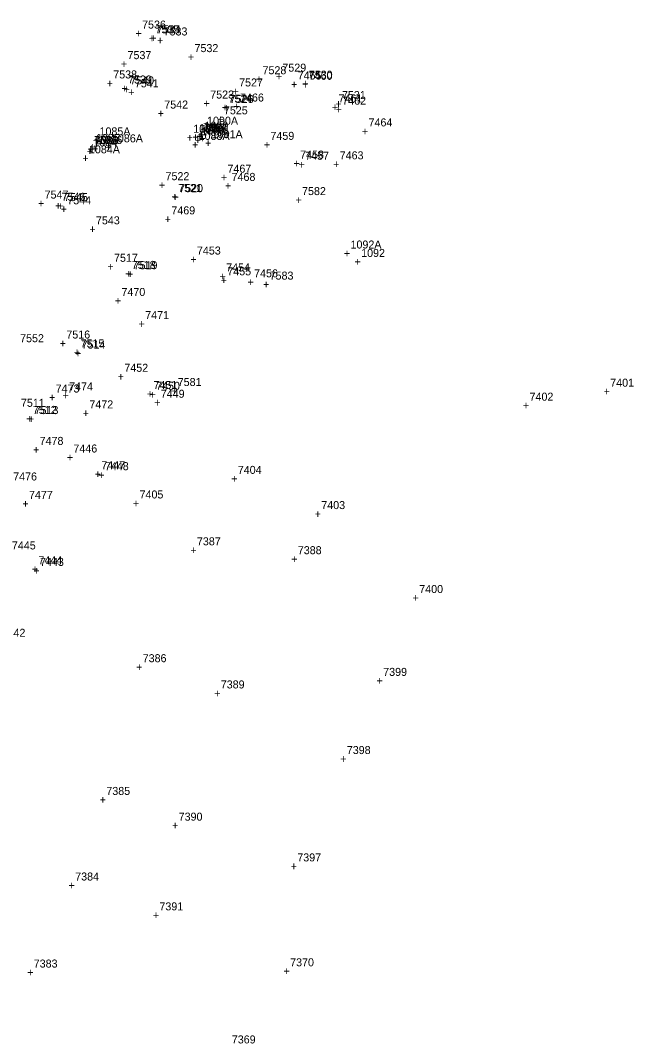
# Model space of a CAD drawing. Extents: x 1136220 to 1137808, y 528804 to 531215.
# Drawn here: x 1137616.8 to 1137808.2, y 530895.5 to 531215.1 of the extents above; entities that cross this region are included whole.
import ezdxf

# ---------------------------------------------------------------- set-up
doc = ezdxf.new("R2010")
doc.units = 0
for name, color, linetype in [('S_Curb_Type_1', 7, 'Continuous'), ('S_Drainage_CB', 7, 'Continuous'), ('S_Drainage_Culvert_Top', 7, 'Continuous'), ('S_Drainage_Invert', 7, 'Continuous'), ('S_Drainage_Sump', 7, 'Continuous'), ('S_Fencing_PostAndRail', 7, 'Continuous'), ('S_Ground_Elevation', 7, 'Continuous'), ('S_Property_IronPipeFound', 7, 'Continuous'), ('S_Property_Walkways', 7, 'Continuous'), ('S_Roadway_Centerline', 7, 'Continuous'), ('S_Roadway_Drive_Paved', 7, 'Continuous'), ('S_Roadway_Edge_Pavement', 7, 'Continuous'), ('S_Roadway_Edge_TW', 7, 'Continuous'), ('S_Roadway_Sidewalks', 7, 'Continuous'), ('S_Traffic_Sign_SinglePost', 7, 'Continuous'), ('S_Trees_Decid_Pay', 7, 'Continuous'), ('S_Trees_TreeLine', 7, 'Continuous'), ('S_Utilities_GuyWire3', 7, 'Continuous'), ('S_Utilities_Pole_Power', 7, 'Continuous')]:
    doc.layers.add(name, color=color, linetype=linetype)

msp = doc.modelspace()

# ---------------------------------------------------------------- texts
at = {"layer": 'S_Curb_Type_1'}
for s, p in [('7535', (1137658.9, 531211.07)), ('+', (1137656.84, 531208.32)), ('7539', (1137650.37, 531195.42)), ('+', (1137648.31, 531192.67)), ('7526', (1137682.11, 531189.32)), ('+', (1137680.05, 531186.57)), ('7525', (1137680.3, 531185.79)), ('+', (1137678.24, 531183.04)), ('7546', (1137629.62, 531158.77)), ('7520', (1137666.34, 531161.47)), ('+', (1137627.56, 531156.02)), ('+', (1137664.28, 531158.72)), ('7519', (1137652.11, 531137.4)), ('+', (1137650.05, 531134.65)), ('7514', (1137635.86, 531112.61)), ('+', (1137633.79, 531109.86)), ('7513', (1137621.18, 531092.15)), ('+', (1137619.12, 531089.4))]:
    msp.add_text(s, height=2.5, dxfattribs=at).set_placement(p)
at = {"layer": 'S_Drainage_CB'}
for s, p in [('7584', (1137673.8, 531180.5)), ('7585', (1137639.8, 531176.5)), ('+', (1137671.74, 531177.75)), ('+', (1137637.74, 531173.75))]:
    msp.add_text(s, height=2.5, dxfattribs=at).set_placement(p)
at = {"layer": 'S_Drainage_Culvert_Top'}
for s, p in [('1090A', (1137675.05, 531182.54)), ('1085A', (1137641.45, 531179.21)), ('1089A', (1137670.74, 531180.03)), ('1088A', (1137672.41, 531177.81)), ('+', (1137672.99, 531179.79)), ('1091A', (1137676.48, 531178.34)), ('+', (1137639.39, 531176.46)), ('1086A', (1137645.34, 531177.04)), ('+', (1137668.68, 531177.28)), ('+', (1137670.35, 531175.06)), ('+', (1137674.42, 531175.59)), ('1084A', (1137638.16, 531173.61)), ('+', (1137643.28, 531174.29)), ('+', (1137636.1, 531170.86)), ('1092A', (1137719.84, 531143.87)), ('+', (1137717.78, 531141.12))]:
    msp.add_text(s, height=2.5, dxfattribs=at).set_placement(p)
at = {"layer": 'S_Drainage_Invert'}
for s, p in [('1090', (1137674.23, 531180.98)), ('+', (1137672.17, 531178.23)), ('1089', (1137672.51, 531180.22)), ('1088', (1137673.25, 531179.23)), ('1091', (1137674.72, 531179.79)), ('1084', (1137639.51, 531175.78)), ('1085', (1137640.33, 531177.15)), ('1086', (1137641.12, 531176.53)), ('+', (1137670.45, 531177.47)), ('+', (1137671.19, 531176.48)), ('+', (1137672.66, 531177.04)), ('+', (1137637.45, 531173.03)), ('+', (1137638.27, 531174.4)), ('+', (1137639.06, 531173.78)), ('1092', (1137723.16, 531141.23)), ('+', (1137721.1, 531138.48))]:
    msp.add_text(s, height=2.5, dxfattribs=at).set_placement(p)
at = {"layer": 'S_Drainage_Sump'}
for s, p in [('1087', (1137673.91, 531180.4)), ('1083', (1137639.91, 531176.4)), ('+', (1137671.85, 531177.65)), ('+', (1137637.85, 531173.65))]:
    msp.add_text(s, height=2.5, dxfattribs=at).set_placement(p)
at = {"layer": 'S_Fencing_PostAndRail'}
for s, p in [('7462', (1137717.27, 531188.81)), ('+', (1137715.2, 531186.06)), ('7457', (1137705.69, 531171.6)), ('+', (1137703.63, 531168.85)), ('7455', (1137681.36, 531135.5)), ('+', (1137679.3, 531132.75)), ('7450', (1137659.13, 531099.74)), ('+', (1137657.07, 531096.99))]:
    msp.add_text(s, height=2.5, dxfattribs=at).set_placement(p)
at = {"layer": 'S_Ground_Elevation'}
for s, p in [('7465', (1137703.34, 531196.67)), ('+', (1137701.28, 531193.92)), ('7466', (1137685.35, 531189.78)), ('+', (1137683.29, 531187.03)), ('7464', (1137725.47, 531182.01)), ('+', (1137723.41, 531179.26)), ('7463', (1137716.46, 531171.73)), ('+', (1137714.4, 531168.98)), ('7468', (1137682.7, 531164.99)), ('+', (1137680.64, 531162.24)), ('7469', (1137663.89, 531154.54)), ('+', (1137661.83, 531151.79)), ('7456', (1137689.73, 531134.88)), ('+', (1137687.66, 531132.13)), ('7470', (1137648.31, 531129.05)), ('+', (1137646.25, 531126.3)), ('7471', (1137655.73, 531121.84)), ('+', (1137653.67, 531119.09)), ('7473', (1137627.75, 531098.89)), ('+', (1137625.69, 531096.14)), ('7449', (1137660.59, 531097.26)), ('7472', (1137638.29, 531093.94)), ('+', (1137658.53, 531094.51)), ('+', (1137636.22, 531091.19)), ('7448', (1137643.13, 531074.63)), ('+', (1137641.07, 531071.88)), ('7477', (1137619.42, 531065.65)), ('+', (1137617.35, 531062.9)), ('7387', (1137671.87, 531051.16)), ('+', (1137669.81, 531048.41)), ('7388', (1137703.38, 531048.39)), ('7443', (1137622.88, 531044.74)), ('+', (1137701.32, 531045.64)), ('+', (1137620.82, 531041.99)), ('7400', (1137741.3, 531036.26)), ('+', (1137739.24, 531033.51)), ('7442', (1137610.87, 531022.59)), ('7386', (1137654.94, 531014.65)), ('+', (1137652.88, 531011.9)), ('7399', (1137730.05, 531010.38)), ('7389', (1137679.32, 531006.46)), ('+', (1137727.99, 531007.63)), ('+', (1137677.26, 531003.71)), ('7398', (1137718.68, 530985.96)), ('+', (1137716.62, 530983.21)), ('7385', (1137643.58, 530973.19)), ('+', (1137641.52, 530970.44)), ('7390', (1137666.17, 530965.16)), ('+', (1137664.11, 530962.41)), ('7397', (1137703.22, 530952.43)), ('+', (1137701.16, 530949.68)), ('7384', (1137633.86, 530946.46)), ('+', (1137631.8, 530943.71)), ('7391', (1137660.16, 530937.13)), ('+', (1137658.1, 530934.38)), ('7383', (1137620.91, 530919.27)), ('7370', (1137700.99, 530919.66)), ('+', (1137618.85, 530916.52)), ('+', (1137698.93, 530916.91)), ('7369', (1137682.77, 530895.57))]:
    msp.add_text(s, height=2.5, dxfattribs=at).set_placement(p)
at = {"layer": 'S_Property_IronPipeFound'}
for s, p in [('7583', (1137694.58, 531134.16)), ('+', (1137692.52, 531131.41))]:
    msp.add_text(s, height=2.5, dxfattribs=at).set_placement(p)
at = {"layer": 'S_Property_Walkways'}
for s, p in [('7460', (1137706.78, 531196.57)), ('+', (1137704.72, 531193.82)), ('7461', (1137716.09, 531189.52)), ('+', (1137714.03, 531186.77)), ('7459', (1137694.83, 531177.82)), ('+', (1137692.77, 531175.07)), ('7458', (1137704.11, 531171.97)), ('+', (1137702.05, 531169.22)), ('7453', (1137671.87, 531141.99)), ('+', (1137669.81, 531139.24)), ('7454', (1137681.01, 531136.71)), ('+', (1137678.95, 531133.96)), ('7452', (1137649.21, 531105.37)), ('+', (1137647.15, 531102.62)), ('7451', (1137658.31, 531099.99)), ('+', (1137656.25, 531097.24)), ('7446', (1137633.3, 531080.15)), ('+', (1137631.24, 531077.4)), ('7447', (1137642.02, 531074.94)), ('+', (1137639.96, 531072.19)), ('7445', (1137614.09, 531049.88)), ('7444', (1137622.37, 531045.24)), ('+', (1137620.31, 531042.49))]:
    msp.add_text(s, height=2.5, dxfattribs=at).set_placement(p)
at = {"layer": 'S_Roadway_Centerline'}
for s, p in [('7532', (1137671.12, 531205.22)), ('+', (1137669.06, 531202.47)), ('7542', (1137661.68, 531187.59)), ('+', (1137659.62, 531184.84)), ('7543', (1137640.34, 531151.43)), ('+', (1137638.28, 531148.68)), ('7552', (1137616.66, 531114.61))]:
    msp.add_text(s, height=2.5, dxfattribs=at).set_placement(p)
at = {"layer": 'S_Roadway_Drive_Paved'}
for s, p in [('7528', (1137692.36, 531198.31)), ('7529', (1137698.56, 531199.12)), ('7530', (1137706.81, 531196.93)), ('+', (1137690.3, 531195.56)), ('+', (1137696.5, 531196.37)), ('+', (1137704.74, 531194.18)), ('7531', (1137717.18, 531190.56)), ('+', (1137715.12, 531187.81))]:
    msp.add_text(s, height=2.5, dxfattribs=at).set_placement(p)
at = {"layer": 'S_Roadway_Edge_Pavement'}
for s, p in [('7534', (1137659.36, 531211.1)), ('+', (1137657.3, 531208.35)), ('7540', (1137651.04, 531195.14)), ('7527', (1137685.05, 531194.5)), ('+', (1137648.97, 531192.39)), ('+', (1137682.98, 531191.75)), ('7524', (1137681.73, 531189.44)), ('+', (1137679.67, 531186.69)), ('7545', (1137630.4, 531158.68)), ('7521', (1137666.04, 531161.54)), ('+', (1137628.34, 531155.93)), ('+', (1137663.98, 531158.79)), ('7518', (1137651.55, 531137.5)), ('+', (1137649.49, 531134.75)), ('7515', (1137635.53, 531112.99)), ('+', (1137633.47, 531110.24)), ('7512', (1137620.64, 531092.21)), ('+', (1137618.58, 531089.46))]:
    msp.add_text(s, height=2.5, dxfattribs=at).set_placement(p)
at = {"layer": 'S_Roadway_Edge_TW'}
for s, p in [('7533', (1137661.47, 531210.43)), ('+', (1137659.41, 531207.68)), ('7541', (1137652.49, 531194.22)), ('+', (1137650.43, 531191.47)), ('7523', (1137676.03, 531190.72)), ('+', (1137673.97, 531187.97)), ('7522', (1137662.07, 531165.22)), ('+', (1137660.01, 531162.47)), ('7544', (1137631.4, 531157.69)), ('+', (1137629.34, 531154.94)), ('7517', (1137645.99, 531139.73)), ('+', (1137643.93, 531136.98)), ('7516', (1137631.1, 531115.75)), ('+', (1137629.04, 531113)), ('7511', (1137616.91, 531094.43))]:
    msp.add_text(s, height=2.5, dxfattribs=at).set_placement(p)
at = {"layer": 'S_Roadway_Sidewalks'}
for s, p in [('7536', (1137654.75, 531212.57)), ('+', (1137652.69, 531209.82)), ('7537', (1137650.2, 531203.03)), ('7538', (1137645.75, 531197)), ('+', (1137648.14, 531200.28)), ('+', (1137643.69, 531194.25)), ('7547', (1137624.3, 531159.46)), ('+', (1137622.24, 531156.71))]:
    msp.add_text(s, height=2.5, dxfattribs=at).set_placement(p)
at = {"layer": 'S_Traffic_Sign_SinglePost'}
for s, p in [('7474', (1137631.96, 531099.53)), ('+', (1137629.89, 531096.78))]:
    msp.add_text(s, height=2.5, dxfattribs=at).set_placement(p)
at = {"layer": 'S_Trees_Decid_Pay'}
for s, p in [('7467', (1137681.42, 531167.57)), ('+', (1137679.36, 531164.82))]:
    msp.add_text(s, height=2.5, dxfattribs=at).set_placement(p)
at = {"layer": 'S_Trees_TreeLine'}
for s, p in [('7582', (1137704.71, 531160.56)), ('+', (1137702.65, 531157.81)), ('7581', (1137665.88, 531100.92)), ('+', (1137663.82, 531098.17)), ('7401', (1137800.95, 531100.71)), ('7402', (1137775.75, 531096.34)), ('+', (1137798.89, 531097.96)), ('+', (1137773.69, 531093.59)), ('7404', (1137684.64, 531073.47)), ('+', (1137682.58, 531070.72)), ('7405', (1137653.96, 531065.8)), ('+', (1137651.9, 531063.05)), ('7403', (1137710.71, 531062.48)), ('+', (1137708.65, 531059.73))]:
    msp.add_text(s, height=2.5, dxfattribs=at).set_placement(p)
at = {"layer": 'S_Utilities_GuyWire3'}
for s, p in [('7478', (1137622.75, 531082.53)), ('+', (1137620.69, 531079.78))]:
    msp.add_text(s, height=2.5, dxfattribs=at).set_placement(p)
at = {"layer": 'S_Utilities_Pole_Power'}
msp.add_text('7476', height=2.5, dxfattribs=at).set_placement((1137614.49, 531071.42))

doc.saveas('drawing.dxf')
